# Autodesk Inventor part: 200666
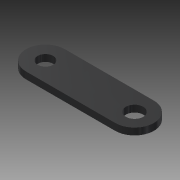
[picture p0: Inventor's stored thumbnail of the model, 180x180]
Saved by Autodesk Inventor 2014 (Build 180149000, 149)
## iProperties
Created: 2007-10
Part Number: 200666
Document SubType Name: Modeling
Designer: TH
Density: 7.85 g/cm^3
Mass: 30.7796 g
Surface Area: 29.6939 cm^2
Volume: 3.92097 cm^3
Material: Steel
Description: LINK PLATE
Appearance: Rubber - Black - Version 1.1
Component Category: Lower Component
Author: TH
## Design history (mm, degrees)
sketch "Sketch1"
  geometry: L1 (0, 0)-(-46, 0); L2 (-46, 10)-(0, 10); L3 (-46, -10)-(0, -10); A1 r 10 centre (0, 0) between (0, -10) and (0, 10); A2 r 10 centre (-46, 0) between (-46, 10) and (-46, -10); 1 further point
  constraints: 6 end point, 4 point on circle, 4 tangent, 2 centre point, 2 coincident, 1 horizontal
  dimensions: "d0" = 20 diameter of A2; "d1" = 20 diameter of A1; "d2" = 46 distance of point (0, 0) L1.end
extrude "Extrusion1" new body sketch "Sketch1" stored distance "d3" = 3.5; taper "d4" = 0 deg
hole "Hole3" diameter "d21" = 8; stored, may be unused: countersink angle "d25" = 90 deg, drill point angle "d27" = 118 deg; dims "d19" = 10, "d20" = 10, "d22" = 6, "d23" = 4, "d24" = 2, "d26" = 8
hole "Hole4" diameter "d30" = 9; stored, may be unused: countersink angle "d34" = 90 deg, drill point angle "d36" = 118 deg; dims "d28" = 10, "d29" = 10, "d31" = 6, "d32" = 4, "d33" = 2, "d35" = 8
body "Solid1"
other parameters: "sa_eq_min" = 29063, "sa_eq_max" = 4727280, "sa_pmax_min" = -126299, "sa_pmax_max" = 2242680, "sa_pmin_min" = -4673200, "sa_pmin_max" = 141331, "sa_d_min" = 0.00001, "sa_d_max" = 0.00273, "sa_sf_min" = 43.7884
